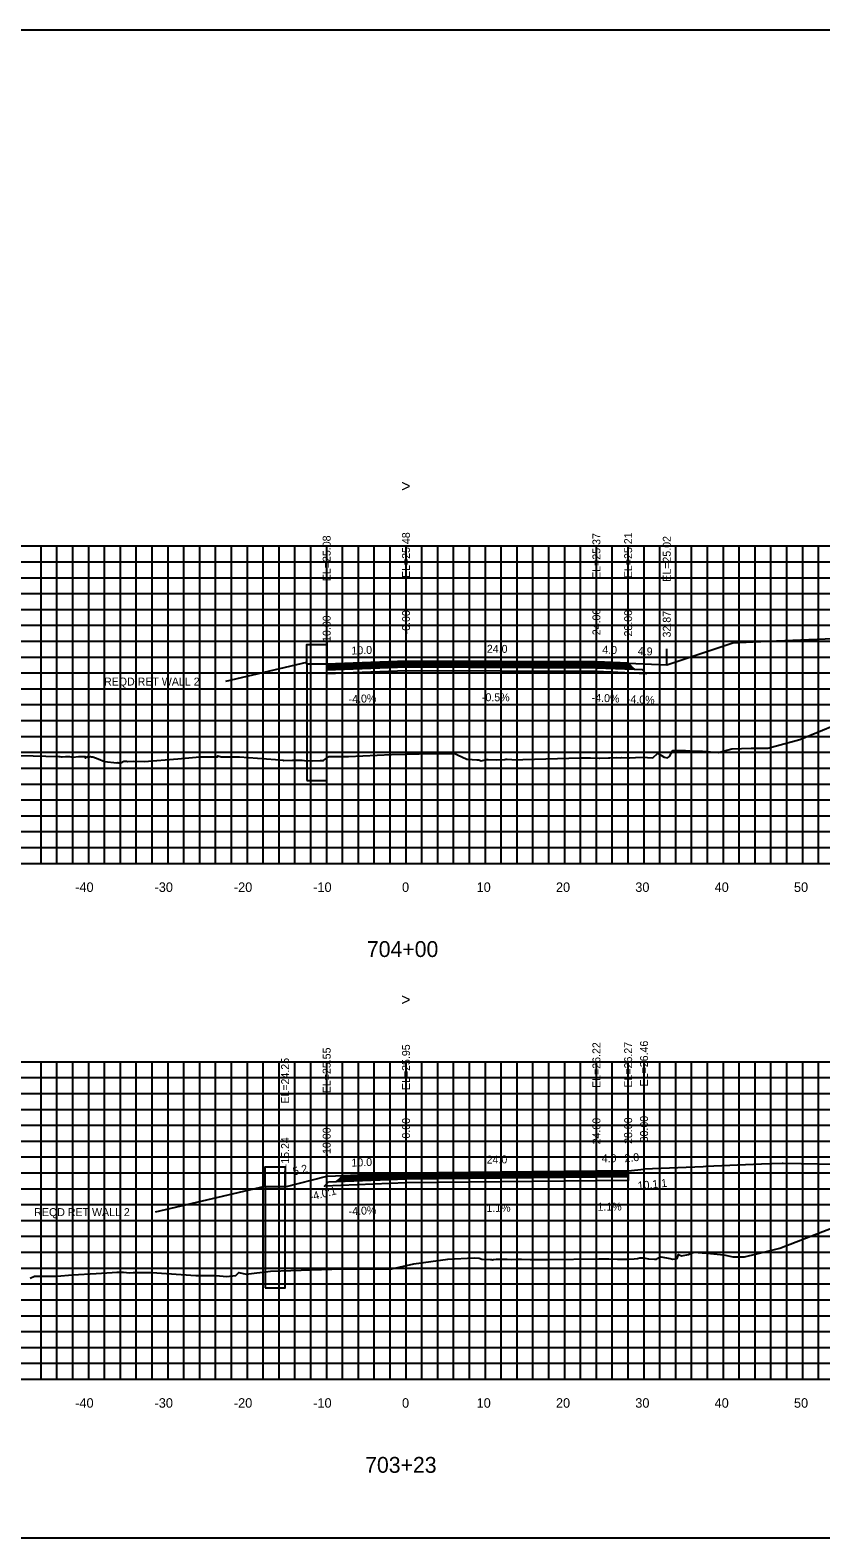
# Model space of a CAD drawing. Extents: x 1797518 to 1804843, y 248068 to 251132.
# Drawn here: x 1802923.6 to 1803023.3, y 250079.4 to 250269.4 of the extents above; entities that cross this region are included whole.
import ezdxf

# ---------------------------------------------------------------- set-up
doc = ezdxf.new("R2010")
doc.units = 0
for name, color, linetype in [('1', 7, 'Continuous'), ('10', 7, 'Continuous'), ('3', 7, 'Continuous'), ('4', 7, 'Continuous'), ('60', 7, 'Continuous'), ('BASE', 7, 'Continuous'), ('CL-CNST', 7, 'Continuous'), ('Level 62', 7, 'Continuous'), ('LOWER BINDER', 7, 'Continuous'), ('M-ROADS', 7, 'Continuous'), ('UPPER BINDER', 7, 'Continuous'), ('WEARING', 7, 'Continuous')]:
    doc.layers.add(name, color=color, linetype=linetype)

msp = doc.modelspace()

# ---------------------------------------------------------------- linework, layer by layer
for p, q in [((1802961, 250189.52), (1802961, 250191.52)), ((1802971, 250189.92), (1802971, 250191.92)), ((1802995, 250189.81), (1802995, 250191.81)), ((1802999, 250189.65), (1802999, 250191.65)), ((1803003.87, 250189.45), (1803003.87, 250191.45)), ((1802995, 250125.65), (1802995, 250127.65)), ((1802999, 250125.7), (1802999, 250127.7)), ((1803001, 250125.9), (1803001, 250127.9)), ((1802955.76, 250123.68), (1802955.76, 250125.68)), ((1802961, 250124.99), (1802961, 250126.99)), ((1802971, 250125.39), (1802971, 250127.39))]:
    msp.add_line(p, q)
msp.add_lwpolyline([(1802821, 250079.43), (1803121, 250079.43), (1803121, 250269.43), (1802821, 250269.43)], close=True)
at = {"layer": '3'}
for p, q in [((1802948.28, 250187.39), (1802958.5, 250189.79)), ((1802939.44, 250120.53), (1802953.26, 250123.76))]:
    msp.add_line(p, q, dxfattribs=at)
at = {"layer": '60'}
for p, q in [((1802821, 250164.43), (1803121, 250164.43)), ((1802931, 250164.37), (1802931, 250164.43)), ((1802941, 250164.37), (1802941, 250164.43)), ((1802951, 250164.37), (1802951, 250164.43)), ((1802961, 250164.37), (1802961, 250164.43)), ((1802971, 250164.37), (1802971, 250164.43)), ((1802981, 250164.37), (1802981, 250164.43)), ((1802991, 250164.37), (1802991, 250164.43)), ((1803001, 250164.37), (1803001, 250164.43)), ((1803011, 250164.37), (1803011, 250164.43)), ((1803021, 250164.37), (1803021, 250164.43)), ((1802821, 250099.43), (1803121, 250099.43)), ((1802931, 250099.37), (1802931, 250099.43)), ((1802941, 250099.37), (1802941, 250099.43)), ((1802951, 250099.37), (1802951, 250099.43)), ((1802961, 250099.37), (1802961, 250099.43)), ((1802971, 250099.37), (1802971, 250099.43)), ((1802981, 250099.37), (1802981, 250099.43)), ((1802991, 250099.37), (1802991, 250099.43)), ((1803001, 250099.37), (1803001, 250099.43)), ((1803011, 250099.37), (1803011, 250099.43)), ((1803021, 250099.37), (1803021, 250099.43))]:
    msp.add_line(p, q, dxfattribs=at)
at = {"layer": 'BASE'}
for points in [[(1802961, 250188.8), (1802971, 250189.2), (1802995, 250189.09), (1802999.75, 250188.9), (1803000.75, 250188.86), (1803001.27, 250188.33), (1802995, 250188.59), (1802971, 250188.7), (1802961, 250188.3)], [(1802961.25, 250124.28), (1802962.25, 250124.32), (1802971, 250124.67), (1802995, 250124.93), (1802999, 250124.98), (1802999, 250124.48), (1802995, 250124.43), (1802971, 250124.17), (1802960.73, 250123.76)]]:
    msp.add_lwpolyline(points, close=True, dxfattribs=at)
at = {"layer": 'CL-CNST'}
for points in [[(1802961, 250189.52), (1802958.5, 250189.52), (1802958.5, 250192.02), (1802961, 250192.02)], [(1802958.5, 250174.87), (1802961, 250174.87), (1802961, 250189.52), (1802958.5, 250189.52)], [(1802955.76, 250123.68), (1802953.26, 250123.68), (1802953.26, 250126.18), (1802955.76, 250126.18)], [(1802953.26, 250110.94), (1802955.76, 250110.94), (1802955.76, 250123.68), (1802953.26, 250123.68)]]:
    msp.add_lwpolyline(points, close=True, dxfattribs=at)
for points in [[(1803003.87, 250189.45), (1803007.17, 250190.55), (1803012.19, 250192.22), (1803015.58, 250192.37), (1803015.72, 250192.37), (1803017.63, 250192.45), (1803017.74, 250192.46), (1803026.84, 250192.84)], [(1802961, 250189.52), (1802971, 250189.92), (1802995, 250189.81), (1802999, 250189.65), (1803003.87, 250189.45)], [(1802955.76, 250123.68), (1802961, 250124.99), (1802971, 250125.39), (1802995, 250125.65), (1802999, 250125.7), (1803001, 250125.9)], [(1803001, 250125.94), (1803008.47, 250126.25), (1803008.8, 250126.26), (1803015.81, 250126.55), (1803018.42, 250126.66), (1803018.54, 250126.66), (1803029.85, 250126.43)]]:
    msp.add_lwpolyline(points, dxfattribs=at)
at = {"layer": 'Level 62'}
for p, q in [((1802821, 250204.43), (1803121, 250204.43)), ((1802925, 250164.43), (1802925, 250204.43)), ((1802927, 250164.43), (1802927, 250204.43)), ((1802929, 250164.43), (1802929, 250204.43)), ((1802931, 250164.43), (1802931, 250204.43)), ((1802933, 250164.43), (1802933, 250204.43)), ((1802935, 250164.43), (1802935, 250204.43)), ((1802937, 250164.43), (1802937, 250204.43)), ((1802939, 250164.43), (1802939, 250204.43)), ((1802941, 250164.43), (1802941, 250204.43)), ((1802943, 250164.43), (1802943, 250204.43)), ((1802945, 250164.43), (1802945, 250204.43)), ((1802947, 250164.43), (1802947, 250204.43)), ((1802949, 250164.43), (1802949, 250204.43)), ((1802951, 250164.43), (1802951, 250204.43)), ((1802953, 250164.43), (1802953, 250204.43)), ((1802955, 250164.43), (1802955, 250204.43)), ((1802957, 250164.43), (1802957, 250204.43)), ((1802959, 250164.43), (1802959, 250204.43)), ((1802961, 250164.43), (1802961, 250204.43)), ((1802963, 250164.43), (1802963, 250204.43)), ((1802965, 250164.43), (1802965, 250204.43)), ((1802967, 250164.43), (1802967, 250204.43)), ((1802969, 250164.43), (1802969, 250204.43)), ((1802971, 250164.43), (1802971, 250204.43)), ((1802973, 250164.43), (1802973, 250204.43)), ((1802975, 250164.43), (1802975, 250204.43)), ((1802977, 250164.43), (1802977, 250204.43)), ((1802979, 250164.43), (1802979, 250204.43)), ((1802981, 250164.43), (1802981, 250204.43)), ((1802983, 250164.43), (1802983, 250204.43)), ((1802985, 250164.43), (1802985, 250204.43)), ((1802987, 250164.43), (1802987, 250204.43)), ((1802989, 250164.43), (1802989, 250204.43)), ((1802991, 250164.43), (1802991, 250204.43)), ((1802993, 250164.43), (1802993, 250204.43)), ((1802995, 250164.43), (1802995, 250204.43)), ((1802997, 250164.43), (1802997, 250204.43)), ((1802999, 250164.43), (1802999, 250204.43)), ((1803001, 250164.43), (1803001, 250204.43)), ((1803003, 250164.43), (1803003, 250204.43)), ((1803005, 250164.43), (1803005, 250204.43)), ((1803007, 250164.43), (1803007, 250204.43)), ((1803009, 250164.43), (1803009, 250204.43)), ((1803011, 250164.43), (1803011, 250204.43)), ((1803013, 250164.43), (1803013, 250204.43)), ((1803015, 250164.43), (1803015, 250204.43)), ((1803017, 250164.43), (1803017, 250204.43)), ((1803019, 250164.43), (1803019, 250204.43)), ((1803021, 250164.43), (1803021, 250204.43)), ((1803023, 250164.43), (1803023, 250204.43)), ((1802821, 250202.43), (1803121, 250202.43)), ((1802821, 250200.43), (1803121, 250200.43)), ((1802821, 250198.43), (1803121, 250198.43)), ((1802821, 250196.43), (1803121, 250196.43)), ((1802821, 250194.43), (1803121, 250194.43)), ((1802821, 250192.43), (1803121, 250192.43)), ((1802821, 250190.43), (1803121, 250190.43)), ((1802821, 250188.43), (1803121, 250188.43)), ((1802821, 250186.43), (1803121, 250186.43)), ((1802821, 250184.43), (1803121, 250184.43)), ((1802821, 250182.43), (1803121, 250182.43)), ((1802821, 250180.43), (1803121, 250180.43)), ((1802821, 250178.43), (1803121, 250178.43)), ((1802821, 250176.43), (1803121, 250176.43)), ((1802821, 250174.43), (1803121, 250174.43)), ((1802821, 250172.43), (1803121, 250172.43)), ((1802821, 250170.43), (1803121, 250170.43)), ((1802821, 250168.43), (1803121, 250168.43)), ((1802821, 250166.43), (1803121, 250166.43)), ((1802821, 250164.43), (1803121, 250164.43)), ((1802821, 250139.43), (1803121, 250139.43)), ((1802925, 250099.43), (1802925, 250139.43)), ((1802927, 250099.43), (1802927, 250139.43)), ((1802929, 250099.43), (1802929, 250139.43)), ((1802931, 250099.43), (1802931, 250139.43)), ((1802933, 250099.43), (1802933, 250139.43)), ((1802935, 250099.43), (1802935, 250139.43)), ((1802937, 250099.43), (1802937, 250139.43)), ((1802939, 250099.43), (1802939, 250139.43)), ((1802941, 250099.43), (1802941, 250139.43)), ((1802943, 250099.43), (1802943, 250139.43)), ((1802945, 250099.43), (1802945, 250139.43)), ((1802947, 250099.43), (1802947, 250139.43)), ((1802949, 250099.43), (1802949, 250139.43)), ((1802951, 250099.43), (1802951, 250139.43)), ((1802953, 250099.43), (1802953, 250139.43)), ((1802955, 250099.43), (1802955, 250139.43)), ((1802957, 250099.43), (1802957, 250139.43)), ((1802959, 250099.43), (1802959, 250139.43)), ((1802961, 250099.43), (1802961, 250139.43)), ((1802963, 250099.43), (1802963, 250139.43)), ((1802965, 250099.43), (1802965, 250139.43)), ((1802967, 250099.43), (1802967, 250139.43)), ((1802969, 250099.43), (1802969, 250139.43)), ((1802971, 250099.43), (1802971, 250139.43)), ((1802973, 250099.43), (1802973, 250139.43)), ((1802975, 250099.43), (1802975, 250139.43)), ((1802977, 250099.43), (1802977, 250139.43)), ((1802979, 250099.43), (1802979, 250139.43)), ((1802981, 250099.43), (1802981, 250139.43)), ((1802983, 250099.43), (1802983, 250139.43)), ((1802985, 250099.43), (1802985, 250139.43)), ((1802987, 250099.43), (1802987, 250139.43)), ((1802989, 250099.43), (1802989, 250139.43)), ((1802991, 250099.43), (1802991, 250139.43)), ((1802993, 250099.43), (1802993, 250139.43)), ((1802995, 250099.43), (1802995, 250139.43)), ((1802997, 250099.43), (1802997, 250139.43)), ((1802999, 250099.43), (1802999, 250139.43)), ((1803001, 250099.43), (1803001, 250139.43)), ((1803003, 250099.43), (1803003, 250139.43)), ((1803005, 250099.43), (1803005, 250139.43)), ((1803007, 250099.43), (1803007, 250139.43)), ((1803009, 250099.43), (1803009, 250139.43)), ((1803011, 250099.43), (1803011, 250139.43)), ((1803013, 250099.43), (1803013, 250139.43)), ((1803015, 250099.43), (1803015, 250139.43)), ((1803017, 250099.43), (1803017, 250139.43)), ((1803019, 250099.43), (1803019, 250139.43)), ((1803021, 250099.43), (1803021, 250139.43)), ((1803023, 250099.43), (1803023, 250139.43)), ((1802821, 250137.43), (1803121, 250137.43)), ((1802821, 250135.43), (1803121, 250135.43)), ((1802821, 250133.43), (1803121, 250133.43)), ((1802821, 250131.43), (1803121, 250131.43)), ((1802821, 250129.43), (1803121, 250129.43)), ((1802821, 250127.43), (1803121, 250127.43)), ((1802821, 250125.43), (1803121, 250125.43)), ((1802821, 250123.43), (1803121, 250123.43)), ((1802821, 250121.43), (1803121, 250121.43)), ((1802821, 250119.43), (1803121, 250119.43)), ((1802821, 250117.43), (1803121, 250117.43)), ((1802821, 250115.43), (1803121, 250115.43)), ((1802821, 250113.43), (1803121, 250113.43)), ((1802821, 250111.43), (1803121, 250111.43)), ((1802821, 250109.43), (1803121, 250109.43)), ((1802821, 250107.43), (1803121, 250107.43)), ((1802821, 250105.43), (1803121, 250105.43)), ((1802821, 250103.43), (1803121, 250103.43)), ((1802821, 250101.43), (1803121, 250101.43)), ((1802821, 250099.43), (1803121, 250099.43))]:
    msp.add_line(p, q, dxfattribs=at)
at = {"layer": 'LOWER BINDER'}
for points in [[(1802971, 250189.58), (1802995, 250189.47), (1802999.36, 250189.29), (1802999.55, 250189.09), (1802995, 250189.28), (1802971, 250189.39), (1802961, 250188.99), (1802961, 250189.18)], [(1802971, 250189.39), (1802995, 250189.28), (1802999.55, 250189.09), (1802999.75, 250188.9), (1802995, 250189.09), (1802971, 250189.2), (1802961, 250188.8), (1802961, 250188.99)], [(1802971, 250124.86), (1802995, 250125.12), (1802999, 250125.17), (1802999, 250124.98), (1802995, 250124.93), (1802971, 250124.67), (1802962.25, 250124.32), (1802962.45, 250124.51)], [(1802971, 250125.05), (1802995, 250125.31), (1802999, 250125.36), (1802999, 250125.17), (1802995, 250125.12), (1802971, 250124.86), (1802962.45, 250124.51), (1802962.65, 250124.71)]]:
    msp.add_lwpolyline(points, close=True, dxfattribs=at)
at = {"layer": 'M-ROADS'}
for points in [[(1802922.37, 250178.01), (1802927.23, 250177.91), (1802927.3, 250177.91), (1802927.36, 250177.91), (1802927.56, 250177.87), (1802927.65, 250177.86), (1802928.06, 250177.88), (1802928.57, 250177.88), (1802928.77, 250177.87), (1802928.79, 250177.87), (1802929, 250177.83), (1802929.73, 250177.9), (1802930.11, 250177.9), (1802930.48, 250177.89), (1802930.52, 250177.88), (1802930.54, 250177.89), (1802930.56, 250177.75), (1802930.64, 250177.72), (1802930.76, 250177.84), (1802930.87, 250177.88), (1802930.9, 250177.87), (1802930.93, 250177.74), (1802930.96, 250177.81), (1802931.25, 250177.88), (1802931.37, 250177.85), (1802931.53, 250177.86), (1802932.19, 250177.62), (1802933.01, 250177.28), (1802934.55, 250177.09), (1802934.69, 250177.13), (1802934.8, 250177.09), (1802934.86, 250177.09), (1802935.04, 250177.12), (1802935.44, 250177.31), (1802935.76, 250177.29), (1802935.9, 250177.27), (1802936.65, 250177.29), (1802938.01, 250177.28), (1802942.24, 250177.61), (1802945.01, 250177.86), (1802946.94, 250177.86), (1802947.12, 250177.86), (1802947.16, 250177.86), (1802947.24, 250177.86), (1802947.27, 250177.97), (1802947.7, 250177.85), (1802947.9, 250177.86), (1802948.96, 250177.85), (1802950.01, 250177.86), (1802954.56, 250177.5), (1802955.51, 250177.43), (1802955.61, 250177.41), (1802956.68, 250177.42), (1802957.72, 250177.42), (1802957.91, 250177.42), (1802958.19, 250177.41), (1802959.21, 250177.34), (1802960.17, 250177.41), (1802960.61, 250177.41), (1802960.68, 250177.48), (1802961.32, 250177.89), (1802962.18, 250177.89), (1802963.75, 250177.9), (1802969.17, 250178.14), (1802974.4, 250178.27), (1802977.23, 250178.22), (1802977.47, 250178.12), (1802978.68, 250177.56), (1802978.74, 250177.55), (1802979.93, 250177.49), (1802980.16, 250177.49), (1802980.47, 250177.35), (1802981.16, 250177.54), (1802981.36, 250177.54), (1802982.41, 250177.49), (1802983.46, 250177.54), (1802983.57, 250177.55), (1802983.68, 250177.56), (1802983.75, 250177.55), (1802984.93, 250177.49), (1802985.74, 250177.52), (1802992.99, 250177.73), (1802993.37, 250177.74), (1802994.24, 250177.75), (1802995.35, 250177.67), (1802995.43, 250177.68), (1802996.53, 250177.72), (1802996.69, 250177.72), (1802997.5, 250177.77), (1802997.99, 250177.73), (1802998.18, 250177.77), (1802998.97, 250177.73), (1802999.15, 250177.71), (1802999.92, 250177.76), (1803001.02, 250177.8), (1803001.42, 250177.76), (1803002.13, 250177.73), (1803002.75, 250178.3), (1803003.54, 250177.83), (1803003.97, 250177.73), (1803004.22, 250177.88), (1803004.62, 250178.64), (1803006.25, 250178.64), (1803007.34, 250178.59), (1803008.37, 250178.55), (1803010.38, 250178.42), (1803012.06, 250178.85), (1803014.52, 250178.94), (1803015.55, 250178.94), (1803016.59, 250178.94), (1803020.65, 250180.05), (1803027.58, 250182.91)], [(1802923.61, 250112.17), (1802924.18, 250112.39), (1802924.32, 250112.4), (1802924.68, 250112.41), (1802925.84, 250112.41), (1802926.98, 250112.4), (1802928.96, 250112.58), (1802931.93, 250112.73), (1802933.97, 250112.86), (1802934.55, 250112.9), (1802934.97, 250112.91), (1802935.37, 250112.9), (1802936.14, 250112.83), (1802936.59, 250112.86), (1802936.83, 250112.86), (1802938.24, 250112.86), (1802938.97, 250112.86), (1802944.5, 250112.5), (1802944.55, 250112.5), (1802944.6, 250112.5), (1802946.68, 250112.48), (1802947.04, 250112.5), (1802947.05, 250112.5), (1802948.39, 250112.36), (1802949.54, 250112.5), (1802949.55, 250112.5), (1802949.92, 250112.87), (1802950.84, 250112.68), (1802953.91, 250113.03), (1802961.65, 250113.28), (1802964.23, 250113.35), (1802965.91, 250113.35), (1802966.62, 250113.35), (1802966.85, 250113.35), (1802966.95, 250113.35), (1802968.41, 250113.35), (1802969.23, 250113.35), (1802971.99, 250113.96), (1802976.29, 250114.57), (1802979.6, 250114.74), (1802980.21, 250114.69), (1802980.55, 250114.54), (1802981.65, 250114.5), (1802981.8, 250114.49), (1802981.9, 250114.47), (1802982.01, 250114.49), (1802982.4, 250114.54), (1802983.07, 250114.57), (1802983.74, 250114.54), (1802984.32, 250114.52), (1802985, 250114.55), (1802985.55, 250114.54), (1802986.65, 250114.5), (1802986.8, 250114.49), (1802988.96, 250114.51), (1802995.32, 250114.6), (1802996.11, 250114.61), (1802996.57, 250114.61), (1802997.66, 250114.55), (1802997.77, 250114.56), (1802998.81, 250114.56), (1802999.02, 250114.57), (1802999.75, 250114.58), (1803000.16, 250114.62), (1803000.49, 250114.73), (1803000.93, 250114.73), (1803001.57, 250114.61), (1803002.32, 250114.55), (1803002.56, 250114.57), (1803002.67, 250114.63), (1803003.12, 250114.86), (1803004.31, 250114.63), (1803004.6, 250114.57), (1803004.96, 250114.61), (1803005.17, 250114.63), (1803005.33, 250115.14), (1803005.72, 250114.97), (1803006.59, 250115.13), (1803007.27, 250115.44), (1803009.4, 250115.25), (1803011.08, 250115.08), (1803012.2, 250114.86), (1803012.95, 250114.86), (1803013.68, 250114.86), (1803016.93, 250115.65), (1803018.11, 250115.94), (1803026.14, 250119.03)]]:
    msp.add_lwpolyline(points, dxfattribs=at)
at = {"layer": 'UPPER BINDER'}
for points in [[(1802999.36, 250189.29), (1802999.16, 250189.49), (1802995, 250189.66), (1802971, 250189.77), (1802961, 250189.37), (1802961, 250189.18), (1802971, 250189.58), (1802995, 250189.47)], [(1802999, 250125.36), (1802999, 250125.55), (1802995, 250125.5), (1802971, 250125.24), (1802962.85, 250124.91), (1802962.65, 250124.71), (1802971, 250125.05), (1802995, 250125.31)]]:
    msp.add_lwpolyline(points, close=True, dxfattribs=at)
at = {"layer": 'WEARING'}
for points in [[(1802999.16, 250189.49), (1802999, 250189.65), (1802995, 250189.81), (1802971, 250189.92), (1802971, 250189.92), (1802961, 250189.52), (1802961, 250189.37), (1802971, 250189.77), (1802995, 250189.66)], [(1802999, 250125.55), (1802999, 250125.7), (1802995, 250125.65), (1802971, 250125.39), (1802963, 250125.07), (1802962.85, 250124.91), (1802971, 250125.24), (1802995, 250125.5)]]:
    msp.add_lwpolyline(points, close=True, dxfattribs=at)

# ---------------------------------------------------------------- texts
for s, rotation, p in [('-4.0:1', 14.0362, (1802958.99, 250121.91)), ('10.1:1', 5.666, (1803000.25, 250123.31))]:
    msp.add_text(s, height=1, rotation=rotation).set_placement(p)
at = {"layer": '1'}
for s, p in [('704+00', (1802966.07, 250152.63)), ('703+23', (1802965.85, 250087.63))]:
    msp.add_text(s, height=2, dxfattribs=at).set_placement(p)
at = {"layer": '10'}
for s, p in [('-40', (1802929.3, 250160.83)), ('-30', (1802939.3, 250160.83)), ('-20', (1802949.3, 250160.83)), ('-10', (1802959.3, 250160.83)), ('0', (1802970.5, 250160.83)), ('10', (1802979.9, 250160.83)), ('20', (1802989.9, 250160.83)), ('30', (1802999.9, 250160.83)), ('40', (1803009.9, 250160.83)), ('50', (1803019.9, 250160.83)), ('-40', (1802929.3, 250095.83)), ('-30', (1802939.3, 250095.83)), ('-20', (1802949.3, 250095.83)), ('-10', (1802959.3, 250095.83)), ('0', (1802970.5, 250095.83)), ('10', (1802979.9, 250095.83)), ('20', (1802989.9, 250095.83)), ('30', (1802999.9, 250095.83)), ('40', (1803009.9, 250095.83)), ('50', (1803019.9, 250095.83))]:
    msp.add_text(s, height=1.2, dxfattribs=at).set_placement(p)
at = {"layer": '3'}
for s, p in [('EL=25.08', (1802961.5, 250199.99)), ('EL=25.48', (1802971.5, 250200.39)), ('EL=25.37', (1802995.5, 250200.28)), ('EL=25.21', (1802999.5, 250200.37)), ('EL=25.02', (1803004.37, 250199.92)), ('-0.00', (1802971.5, 250193.29)), ('24.00', (1802995.5, 250193.18)), ('28.00', (1802999.5, 250193.02)), ('32.87', (1803004.37, 250192.9)), ('-10.00', (1802961.5, 250191.89)), ('EL=25.55', (1802961.5, 250135.46)), ('EL=25.95', (1802971.5, 250135.86)), ('EL=26.22', (1802995.5, 250136.13)), ('EL=26.27', (1802999.5, 250136.17)), ('EL=26.46', (1803001.5, 250136.32)), ('EL=24.25', (1802956.26, 250134.15)), ('0.00', (1802971.5, 250129.75)), ('24.00', (1802995.5, 250129.02)), ('28.00', (1802999.5, 250129.07)), ('30.00', (1803001.5, 250129.27)), ('-15.24', (1802956.26, 250126.13)), ('-10.00', (1802961.5, 250127.36))]:
    msp.add_text(s, height=1, rotation=90, dxfattribs=at).set_placement(p)
for p in [(1802932.94, 250186.84), (1802924.14, 250119.98)]:
    msp.add_text('REQD RET WALL 2', height=1, dxfattribs=at).set_placement(p)
at = {"layer": '4'}
for s, rotation, p in [('10.0', 2.2906, (1802964.14, 250190.74)), ('24.0', 359.7365, (1802981.19, 250190.97)), ('4.0', 357.7094, (1802995.72, 250190.88)), ('4.9', 357.7094, (1803000.2, 250190.7)), ('-4.0%', 2.2906, (1802963.79, 250184.62)), ('-0.5%', 359.7365, (1802980.57, 250184.87)), ('-4.0%', 357.7094, (1802994.39, 250184.83)), ('-4.0%', 357.7094, (1802998.83, 250184.65)), ('24.0', 0.6357, (1802981.17, 250126.6)), ('4.0', 0.6357, (1802995.67, 250126.76)), ('2.0', 5.666, (1802998.58, 250126.76)), ('5.2', 14.0362, (1802956.87, 250125.09)), ('10.0', 2.2906, (1802964.14, 250126.21)), ('-4.0%', 2.2906, (1802963.79, 250120.09)), ('1.1%', 0.6357, (1802981.14, 250120.5)), ('1.1%', 0.6357, (1802995.14, 250120.65))]:
    msp.add_text(s, height=1, rotation=rotation, dxfattribs=at).set_placement(p)
at = {"layer": '60'}
for p in [(1802970.39, 250211.25), (1802970.39, 250146.53)]:
    msp.add_text('>', height=1.5, dxfattribs=at).set_placement(p)

doc.saveas('drawing.dxf')
